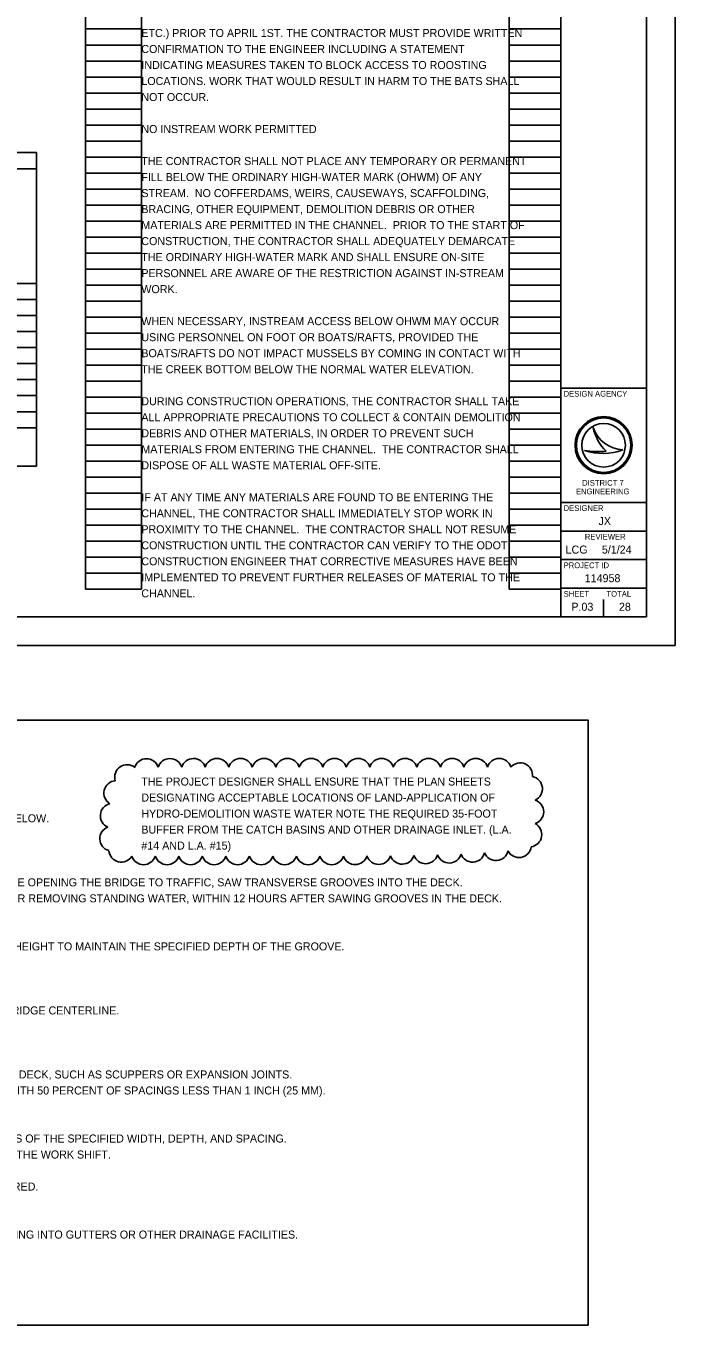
# Model space of a CAD drawing. Extents: x -49 to 78, y -12 to 34.
# Drawn here: x 22.64 to 34, y -11.89 to 10.83 of the extents above; entities that cross this region are included whole.
import ezdxf

# ---------------------------------------------------------------- set-up
doc = ezdxf.new("R2010")
doc.units = 0
for name, color, linetype in [('SC_Scratch1', 7, 'Continuous'), ('SH_Border', 7, 'Continuous'), ('SH_Cut_Line', 7, 'Continuous'), ('SH_Data', 7, 'Continuous'), ('SH_Text', 7, 'Continuous')]:
    doc.layers.add(name, color=color, linetype=linetype)

msp = doc.modelspace()

# ---------------------------------------------------------------- linework, layer by layer
at = {"layer": 'SC_Scratch1'}
for p, q in [((23.68, 0.98), (23.68, 21.14)), ((24.66, 0.98), (24.66, 21.14)), ((31.1, 0.98), (31.1, 21.14)), ((32, 0.98), (32, 21.14)), ((23.68, 10.78), (24.66, 10.78)), ((31.1, 10.78), (32, 10.78)), ((23.68, 10.5), (24.66, 10.5)), ((31.1, 10.5), (32, 10.5)), ((23.68, 10.22), (24.66, 10.22)), ((31.1, 10.22), (32, 10.22)), ((23.68, 9.94), (24.66, 9.94)), ((31.1, 9.94), (32, 9.94)), ((23.68, 9.66), (24.66, 9.66)), ((31.1, 9.66), (32, 9.66)), ((23.68, 9.38), (24.66, 9.38)), ((31.1, 9.38), (32, 9.38)), ((23.68, 9.1), (24.66, 9.1)), ((31.1, 9.1), (32, 9.1)), ((23.68, 8.82), (24.66, 8.82)), ((31.1, 8.82), (32, 8.82)), ((23.68, 8.54), (24.66, 8.54)), ((31.1, 8.54), (32, 8.54)), ((23.68, 8.26), (24.66, 8.26)), ((31.1, 8.26), (32, 8.26)), ((23.68, 7.98), (24.66, 7.98)), ((31.1, 7.98), (32, 7.98)), ((23.68, 7.7), (24.66, 7.7)), ((31.1, 7.7), (32, 7.7)), ((23.68, 7.42), (24.66, 7.42)), ((31.1, 7.42), (32, 7.42)), ((23.68, 7.14), (24.66, 7.14)), ((31.1, 7.14), (32, 7.14)), ((23.68, 6.86), (24.66, 6.86)), ((31.1, 6.86), (32, 6.86)), ((23.68, 6.58), (24.66, 6.58)), ((31.1, 6.58), (32, 6.58)), ((23.68, 6.3), (24.66, 6.3)), ((31.1, 6.3), (32, 6.3)), ((23.68, 6.02), (24.66, 6.02)), ((31.1, 6.02), (32, 6.02)), ((23.68, 5.74), (24.66, 5.74)), ((31.1, 5.74), (32, 5.74)), ((23.68, 5.46), (24.66, 5.46)), ((31.1, 5.46), (32, 5.46)), ((23.68, 5.18), (24.66, 5.18)), ((31.1, 5.18), (32, 5.18)), ((23.68, 4.9), (24.66, 4.9)), ((31.1, 4.9), (32, 4.9)), ((23.68, 4.62), (24.66, 4.62)), ((31.1, 4.62), (32, 4.62)), ((23.68, 4.34), (24.66, 4.34)), ((31.1, 4.34), (32, 4.34)), ((23.68, 4.06), (24.66, 4.06)), ((31.1, 4.06), (32, 4.06)), ((23.68, 3.78), (24.66, 3.78)), ((31.1, 3.78), (32, 3.78)), ((23.68, 3.5), (24.66, 3.5)), ((31.1, 3.5), (32, 3.5)), ((23.68, 3.22), (24.66, 3.22)), ((31.1, 3.22), (32, 3.22)), ((23.68, 2.94), (24.66, 2.94)), ((31.1, 2.94), (32, 2.94)), ((23.68, 2.66), (24.66, 2.66)), ((31.1, 2.66), (32, 2.66)), ((23.68, 2.38), (24.66, 2.38)), ((31.1, 2.38), (32, 2.38)), ((23.68, 2.1), (24.66, 2.1)), ((31.1, 2.1), (32, 2.1)), ((23.68, 1.82), (24.66, 1.82)), ((31.1, 1.82), (32, 1.82)), ((23.68, 1.54), (24.66, 1.54)), ((31.1, 1.54), (32, 1.54)), ((23.68, 1.26), (24.66, 1.26)), ((31.1, 1.26), (32, 1.26)), ((23.68, 0.98), (24.66, 0.98)), ((31.1, 0.98), (32, 0.98))]:
    msp.add_line(p, q, dxfattribs=at)
at = {"layer": 'SH_Border'}
for p, q in [((32, 0.5), (32, 21.5)), ((32, 4.5), (33.5, 4.5)), ((32, 2.5), (33.5, 2.5)), ((32, 2), (33.5, 2)), ((32, 1.5), (33.5, 1.5)), ((32, 1), (33.5, 1))]:
    msp.add_line(p, q, dxfattribs=at)
msp.add_lwpolyline([(1.5, 21.5), (33.5, 21.5), (33.5, 0.5), (1.5, 0.5)], close=True, dxfattribs=at)
at = {"layer": 'SH_Cut_Line'}
msp.add_lwpolyline([(0, 0), (34, 0), (34, 22), (0, 22)], close=True, dxfattribs=at)
at = {"layer": 'SH_Data'}
for p, q in [((9.434, 8.617), (22.825, 8.617)), ((22.825, 8.617), (22.825, 3.132)), ((15.001, 8.337), (22.825, 8.337)), ((15.001, 6.327), (22.825, 6.327)), ((9.434, 6.047), (22.825, 6.047)), ((9.434, 5.767), (22.825, 5.767)), ((9.434, 5.487), (22.825, 5.487)), ((9.434, 5.207), (22.825, 5.207)), ((9.434, 4.927), (22.825, 4.927)), ((9.434, 4.647), (22.825, 4.647)), ((9.434, 4.367), (22.825, 4.367)), ((9.434, 4.087), (22.825, 4.087)), ((9.434, 3.807), (22.825, 3.807)), ((32.567, 3.81), (32.567, 3.81)), ((32.417, 3.41), (32.417, 3.41)), ((32.75, 3.5), (32.75, 3.5)), ((33.087, 3.419), (33.087, 3.419)), ((9.434, 3.132), (22.825, 3.132)), ((32.75, 0.5), (32.75, 0.8)), ((32.375, 0.675), (32.375, 0.675))]:
    msp.add_line(p, q, dxfattribs=at)
for radius in [0.5, 0.477, 0.477, 0.382]:
    msp.add_circle((32.75, 3.5), radius, dxfattribs=at)
for centre, radius, start, end in [((33.116, 3.998), 0.58, 198.9257, 198.9319), ((33.347, 3.97), 0.796, 191.6379, 191.6421), ((33.116, 3.998), 0.58, 198.9319, 267.1657), ((33.347, 3.97), 0.796, 191.6421, 226.0947), ((32.739, 4.37), 1.013, 251.4576, 290.0832), ((32.648, 4.654), 1.266, 259.4964, 259.4995), ((32.739, 4.37), 1.013, 251.4527, 251.4576), ((32.648, 4.654), 1.266, 259.4995, 276.6672)]:
    msp.add_arc(centre, radius, start, end, dxfattribs=at)
at = {"layer": 'SH_Text'}
msp.add_lwpolyline([(6.87, -1.307), (32.478, -1.307), (32.478, -11.887), (6.87, -11.887)], close=True, dxfattribs=at)
for centre, start, end in [((24.749, -2.198), 17.6911, 162.6911), ((25.161, -2.196), 17.8438, 162.8438), ((25.572, -2.195), 17.6225, 162.6225), ((25.984, -2.194), 17.5726, 162.5726), ((26.395, -2.194), 17.5465, 162.5465), ((26.807, -2.193), 17.5297, 162.5297), ((27.218, -2.193), 17.5177, 162.5177), ((27.63, -2.193), 17.5086, 162.5086), ((28.041, -2.193), 17.5017, 162.5017), ((28.453, -2.193), 17.5, 162.5), ((28.865, -2.193), 17.5, 162.5), ((29.276, -2.193), 17.5, 162.5), ((29.688, -2.193), 17.5, 162.5), ((30.099, -2.193), 17.5, 162.5), ((30.511, -2.193), 17.5, 162.5), ((30.923, -2.193), 17.5, 162.5), ((24.411, -2.304), 52.1646, 197.1646), ((31.29, -2.271), 353.3659, 138.3659), ((24.221, -2.583), 94.4724, 239.4724), ((31.463, -2.508), 293.9074, 78.9074), ((31.485, -2.911), 287.5, 72.5), ((24.158, -2.98), 102.4893, 247.4893), ((24.149, -3.382), 109.8181, 254.8181), ((31.452, -3.309), 277.8851, 62.8851), ((24.308, -3.575), 184.231, 329.231), ((30.457, -3.575), 200.3702, 345.3702), ((30.866, -3.548), 202.1105, 347.1105), ((31.267, -3.495), 207.7724, 352.7724), ((24.699, -3.62), 197.5, 342.5), ((25.11, -3.62), 197.5, 342.5), ((25.522, -3.62), 197.5, 342.5), ((25.933, -3.62), 197.5, 342.5), ((26.345, -3.62), 197.5, 342.5), ((26.757, -3.62), 197.5, 342.5), ((27.168, -3.62), 197.5, 342.5), ((27.58, -3.62), 197.5, 342.5), ((27.991, -3.62), 197.543, 342.543), ((28.403, -3.619), 197.7527, 342.7527), ((28.814, -3.616), 198.0227, 343.0227), ((29.225, -3.611), 198.362, 343.362), ((29.636, -3.603), 198.8061, 343.8061), ((30.047, -3.592), 199.4239, 344.4239)]:
    msp.add_arc(centre, 0.216, start, end, dxfattribs=at)

# ---------------------------------------------------------------- texts
at = {"layer": 'SH_Data'}
for s, height, p in [('DESIGN AGENCY', 0.1, (32.05, 4.35)), ('DESIGNER', 0.1, (32.05, 2.35)), ('JX', 0.14, (32.661, 2.105)), ('REVIEWER', 0.1, (32.422, 1.85)), ('LCG', 0.14, (32.085, 1.605)), ('5/1/24', 0.14, (32.719, 1.605)), ('PROJECT ID', 0.1, (32.05, 1.35)), ('114958', 0.14, (32.419, 1.105)), ('SHEET', 0.1, (32.05, 0.85)), ('TOTAL', 0.1, (32.8, 0.85)), ('P.03', 0.14, (32.185, 0.605)), ('28', 0.14, (33.018, 0.605))]:
    msp.add_text(s, height=height, dxfattribs=at).set_placement(p)
at = {"layer": 'SH_Text'}
for s, height, p in [('ETC.) PRIOR TO APRIL 1ST. THE CONTRACTOR MUST PROVIDE WRITTEN ', 0.14, (24.66, 10.64)), ('CONFIRMATION TO THE ENGINEER INCLUDING A STATEMENT ', 0.14, (24.66, 10.36)), ('INDICATING MEASURES TAKEN TO BLOCK ACCESS TO ROOSTING ', 0.14, (24.66, 10.08)), ('LOCATIONS. WORK THAT WOULD RESULT IN HARM TO THE BATS SHALL ', 0.14, (24.66, 9.8)), ('NOT OCCUR.', 0.14, (24.66, 9.52)), ('NO INSTREAM WORK PERMITTED', 0.14, (24.66, 8.96)), ('THE CONTRACTOR SHALL NOT PLACE ANY TEMPORARY OR PERMANENT ', 0.14, (24.66, 8.4)), ('FILL BELOW THE ORDINARY HIGH-WATER MARK (OHWM) OF ANY ', 0.14, (24.66, 8.12)), ('STREAM.  NO COFFERDAMS, WEIRS, CAUSEWAYS, SCAFFOLDING, ', 0.14, (24.66, 7.84)), ('BRACING, OTHER EQUIPMENT, DEMOLITION DEBRIS OR OTHER ', 0.14, (24.66, 7.56)), ('MATERIALS ARE PERMITTED IN THE CHANNEL.  PRIOR TO THE START OF ', 0.14, (24.66, 7.28)), ('CONSTRUCTION, THE CONTRACTOR SHALL ADEQUATELY DEMARCATE ', 0.14, (24.66, 7)), ('THE ORDINARY HIGH-WATER MARK AND SHALL ENSURE ON-SITE ', 0.14, (24.66, 6.72)), ('PERSONNEL ARE AWARE OF THE RESTRICTION AGAINST IN-STREAM ', 0.14, (24.66, 6.44)), ('WORK.  ', 0.14, (24.66, 6.16)), ('WHEN NECESSARY, INSTREAM ACCESS BELOW OHWM MAY OCCUR ', 0.14, (24.66, 5.6)), ('USING PERSONNEL ON FOOT OR BOATS/RAFTS, PROVIDED THE ', 0.14, (24.66, 5.32)), ('BOATS/RAFTS DO NOT IMPACT MUSSELS BY COMING IN CONTACT WITH ', 0.14, (24.66, 5.04)), ('THE CREEK BOTTOM BELOW THE NORMAL WATER ELEVATION.', 0.14, (24.66, 4.76)), ('DURING CONSTRUCTION OPERATIONS, THE CONTRACTOR SHALL TAKE ', 0.14, (24.66, 4.2)), ('ALL APPROPRIATE PRECAUTIONS TO COLLECT & CONTAIN DEMOLITION ', 0.14, (24.66, 3.92)), ('DEBRIS AND OTHER MATERIALS, IN ORDER TO PREVENT SUCH ', 0.14, (24.66, 3.64)), ('MATERIALS FROM ENTERING THE CHANNEL.  THE CONTRACTOR SHALL ', 0.14, (24.66, 3.36)), ('DISPOSE OF ALL WASTE MATERIAL OFF-SITE.  ', 0.14, (24.66, 3.08)), ('ENGINEERING', 0.1, (32.265, 2.642)), ('DISTRICT 7', 0.1, (32.374, 2.792)), ('IF AT ANY TIME ANY MATERIALS ARE FOUND TO BE ENTERING THE ', 0.14, (24.66, 2.52)), ('CHANNEL, THE CONTRACTOR SHALL IMMEDIATELY STOP WORK IN ', 0.14, (24.66, 2.24)), ('PROXIMITY TO THE CHANNEL.  THE CONTRACTOR SHALL NOT RESUME ', 0.14, (24.66, 1.96)), ('CONSTRUCTION UNTIL THE CONTRACTOR CAN VERIFY TO THE ODOT ', 0.14, (24.66, 1.68)), ('CONSTRUCTION ENGINEER THAT CORRECTIVE MEASURES HAVE BEEN ', 0.14, (24.66, 1.4)), ('IMPLEMENTED TO PREVENT FURTHER RELEASES OF MATERIAL TO THE ', 0.14, (24.66, 1.12)), ('CHANNEL.', 0.14, (24.66, 0.84)), ('THE PROJECT DESIGNER SHALL ENSURE THAT THE PLAN SHEETS ', 0.14, (24.66, -2.452)), ('DESIGNATING ACCEPTABLE LOCATIONS OF LAND-APPLICATION OF ', 0.14, (24.66, -2.732)), ('PLACE, CONSOLIDATE AND FINISH OVERLAY AS PER 848.26 WITH THE EXCEPTION THAT THE OVERLAY SHALL BE GROOVED TRANSVERSELY AS DESCRIBED BELOW. ', 0.14, (7.848, -3.095)), ('HYDRO-DEMOLITION WASTE WATER NOTE THE REQUIRED 35-FOOT ', 0.14, (24.66, -3.012)), ('BUFFER FROM THE CATCH BASINS AND OTHER DRAINAGE INLET. (L.A. ', 0.14, (24.66, -3.292)), ('#14 AND L.A. #15)', 0.14, (24.66, -3.572)), ('AFTER WATER CURING CONCRETE AND EITHER BEFORE APPLYING CURING COMPOUND OR SOME PERIOD AFTER APPLYING CURING COMPOUND AND BEFORE OPENING THE BRIDGE TO TRAFFIC, SAW TRANSVERSE GROOVES INTO THE DECK.', 0.14, (7.848, -4.215)), ('IF SAWING GROOVES AFTER APPLYING THE CURING COMPOUND, AND CONCRETE DECK IS LESS THAN 30 DAYS OLD, REAPPLY THE CURING COMPOUND AFTER REMOVING STANDING WATER, WITHIN 12 HOURS AFTER SAWING GROOVES IN THE DECK.', 0.14, (7.848, -4.495)), ('THE GROOVE MACHINE SHALL HAVE A DEPTH CONTROL DEVICE THAT DETECTS VARIATIONS IN THE PAVEMENT SURFACE AND ADJUSTS THE CUTTING HEAD HEIGHT TO MAINTAIN THE SPECIFIED DEPTH OF THE GROOVE.', 0.14, (7.848, -5.335)), ('BEGIN AND END GROOVES 9 TO 12 INCHES (220 TO 300 MM) FROM CURBS, PARAPET TOES, OR DECK EDGES, AND SAW GROOVES PERPENDICULAR TO THE BRIDGE CENTERLINE.', 0.14, (7.848, -6.455)), ('SAW GROOVES IN A CONTINUOUS PATTERN ACROSS THE SURFACE.\xa0STOP SAWING 9 TO 12 INCHES (220 TO 300 MM) FROM ANY DEVICE IN PLACE IN A BRIDGE DECK, SUCH AS SCUPPERS OR EXPANSION JOINTS.', 0.14, (7.848, -7.575)), ('STOP SAWING 2 INCHES TO 2 FEET FROM SKEWED EXPANSION JOINTS. SAW GROOVES IN A RANDOM PATTERN SPACED AT 3/8 TO 1 3/4 INCH (10 TO 45 MM), WITH 50 PERCENT OF SPACINGS LESS THAN 1 INCH (25 MM).', 0.14, (7.848, -7.855)), ('AT THE BEGINNING OF EACH WORK SHIFT, FURNISH A FULL COMPLEMENT OF GROOVING BLADES WITH EACH SAW THAT ARE CAPABLE OF CUTTING GROOVES OF THE SPECIFIED WIDTH, DEPTH, AND SPACING.', 0.14, (7.848, -8.695)), ('IF DURING THE WORK, A SINGLE GROOVING BLADE ON A MACHINE BECOMES INCAPABLE OF CUTTING A GROOVE, CONTINUE WORK FOR THE REMAINDER OF THE WORK SHIFT.', 0.14, (7.848, -8.975)), ('SHOULD TWO OR MORE GROOVING BLADES ON A MACHINE BECOME INCAPABLE OF CUTTING GROOVES, CEASE OPERATING THE MACHINE UNTIL IT IS REPAIRED.', 0.14, (7.848, -9.535)), ('PREVENT RESIDUE FROM GROOVING OPERATIONS FROM FLOWING ACROSS SHOULDERS OR ACROSS LANES OCCUPIED BY PUBLIC TRAFFIC OR FROM FLOWING INTO GUTTERS OR OTHER DRAINAGE FACILITIES.', 0.14, (7.848, -10.375))]:
    msp.add_text(s, height=height, dxfattribs=at).set_placement(p)

doc.saveas('drawing.dxf')
